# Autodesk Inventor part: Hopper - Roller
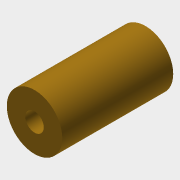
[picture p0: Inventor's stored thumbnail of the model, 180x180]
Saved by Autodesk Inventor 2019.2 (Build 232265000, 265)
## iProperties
Created: 2005-11
Part Number: Hopper - Roller
Document SubType Name: Modeling
Designer: floress
Material: Default
Density: 1 g/cm^3
Appearance: Brass - Satin
Author: floress
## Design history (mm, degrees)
sketch "Sketch1"
  geometry: C1 r 0.794 at (0, 0); C2 r 2.381 at (0, 0)
  constraints: 2 centre point, 1 coincident
  dimensions: "d0" = 1.5875 diameter of C1; "d1" = 4.7625 diameter of C2
extrude "Extrusion1" new body sketch "Sketch1" distance "d2" = 9.525; taper "d3" = 0 deg
body "Solid1"
